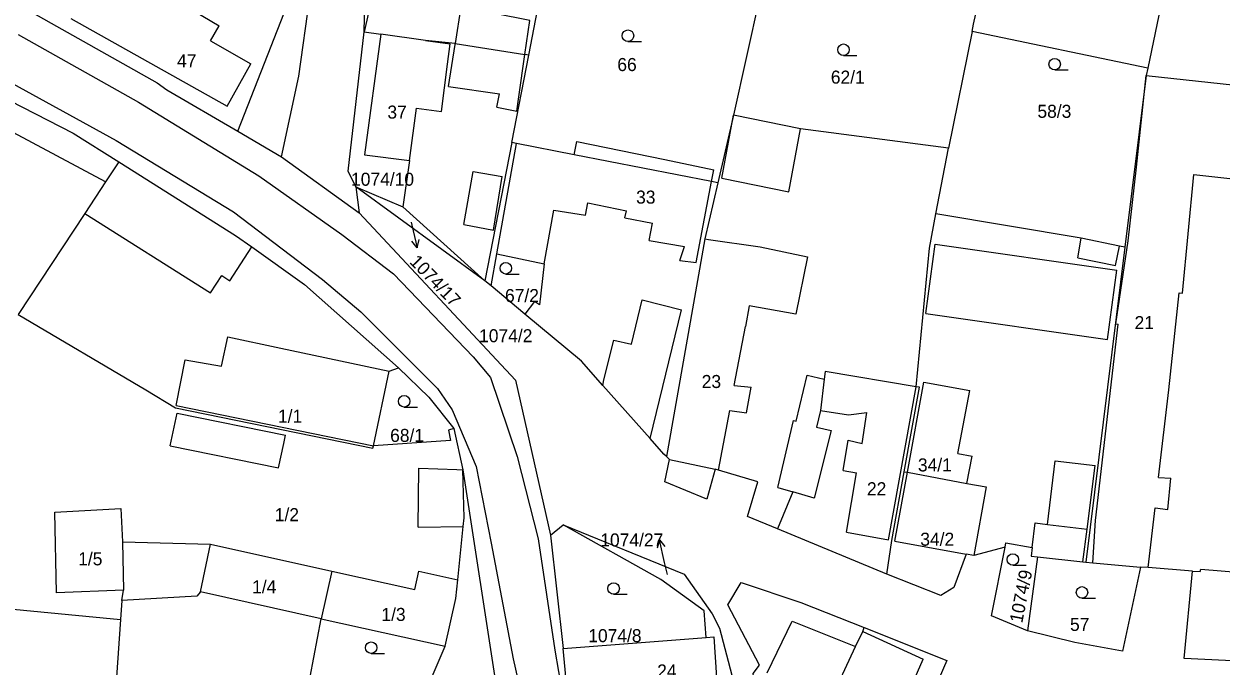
# Model space of a CAD drawing. Extents: x -746176 to -739709, y -1128407 to -1124482.
# Drawn here: x -742393.3 to -742237.2, y -1126052.3 to -1125968.5 of the extents above; entities that cross this region are included whole.
import ezdxf

# ---------------------------------------------------------------- set-up
doc = ezdxf.new("R2010")
doc.units = 0
for name, color, linetype in [('Hranice parcel', 7, 'Continuous'), ('Parcelní čísla', 7, 'Continuous'), ('Pop  PČ popisy', 7, 'Continuous'), ('Vnitřní kresba', 7, 'Continuous'), ('Značky kultur', 7, 'Continuous')]:
    doc.layers.add(name, color=color, linetype=linetype)

msp = doc.modelspace()

# ---------------------------------------------------------------- linework, layer by layer
at = {"layer": 'Hranice parcel'}
for p, q in [((-742296.81, -1125962.38), (-742300.78, -1125980.44)), ((-742244.64, -1125964.23), (-742246.75, -1125974.33)), ((-742348.95, -1125969.57), (-742346.78, -1125969.9)), ((-742269.67, -1125969.51), (-742272.76, -1125984.75)), ((-742246.75, -1125974.33), (-742269.67, -1125969.51)), ((-742329.7, -1125984.02), (-742327.47, -1125972.62)), ((-742246.94, -1125975.25), (-742249.72, -1125997.65)), ((-742246.75, -1125974.33), (-742246.94, -1125975.25)), ((-742246.94, -1125975.25), (-742222.55, -1125977.95)), ((-742300.78, -1125980.44), (-742302.83, -1125989.25)), ((-742329.7, -1125984.02), (-742333.21, -1126002.03)), ((-742274.38, -1125993.3), (-742272.76, -1125984.75)), ((-742380.97, -1125986.53), (-742382.69, -1125989.14)), ((-742350.03, -1125989.81), (-742343.92, -1125992.41)), ((-742333.21, -1126002.03), (-742350.03, -1125989.81)), ((-742350.03, -1125989.81), (-742349.63, -1125993.16)), ((-742343.92, -1125992.41), (-742333.21, -1126002.03)), ((-742275.24, -1125997.79), (-742274.38, -1125993.3)), ((-742276.95, -1126015.87), (-742275.24, -1125997.79)), ((-742249.72, -1125997.65), (-742254.82, -1126038.74)), ((-742332.39, -1126002.71), (-742333.21, -1126002.03)), ((-742327.99, -1126006.38), (-742332.39, -1126002.71)), ((-742337.26, -1126021.33), (-742336.07, -1126026.71)), ((-742336.07, -1126026.71), (-742330.17, -1126065.29)), ((-742324.67, -1126035.23), (-742323.01, -1126033.89)), ((-742280.77, -1126040.3), (-742295.06, -1126034.41)), ((-742324.67, -1126035.23), (-742323.01, -1126050.01)), ((-742265.36, -1126036.8), (-742269.44, -1126037.88)), ((-742261.12, -1126038.05), (-742262.44, -1126047.69)), ((-742353.18, -1126039.91), (-742354.56, -1126046.13)), ((-742354.56, -1126046.13), (-742370.32, -1126042.62)), ((-742356, -1126053.72), (-742354.56, -1126046.13)), ((-742354.56, -1126046.13), (-742338.41, -1126049.72)), ((-742323.01, -1126050.01), (-742304.36, -1126048.56)), ((-742341.65, -1126057.29), (-742338.41, -1126049.72))]:
    msp.add_line(p, q, dxfattribs=at)
for points in [[(-742348.95, -1125969.57), (-742348.77, -1125961.93), (-742341.73, -1125932.77)], [(-742444.75, -1125953.11), (-742386.93, -1125982.77), (-742380.97, -1125986.53)], [(-742345.34, -1125953.5), (-742347.31, -1125962.26), (-742348.95, -1125969.57)], [(-742382.69, -1125989.14), (-742398.6, -1125980.67), (-742445.94, -1125955.65)], [(-742327.47, -1125972.62), (-742326.77, -1125969.01), (-742324.69, -1125958.1)], [(-742365.43, -1125982.55), (-742356.37, -1125959.31), (-742357.41, -1125958.73)], [(-742269.67, -1125969.51), (-742269.48, -1125968.58), (-742268.65, -1125964.88)], [(-742392.86, -1125966.72), (-742375.94, -1125976.23), (-742374.7, -1125977.14), (-742365.43, -1125982.55)], [(-742327.47, -1125972.62), (-742328.01, -1125972.53), (-742327.37, -1125968.09), (-742336.35, -1125966.33), (-742337.09, -1125971.11), (-742340.95, -1125970.71), (-742346.78, -1125969.9)], [(-742350.03, -1125989.81), (-742351.04, -1125987.76), (-742348.95, -1125969.57)], [(-742346.78, -1125969.9), (-742348.93, -1125985.62), (-742343.03, -1125986.37), (-742343.92, -1125992.41)], [(-742272.76, -1125984.75), (-742292.04, -1125982.23), (-742300.78, -1125980.44)], [(-742365.43, -1125982.55), (-742359.74, -1125985.87), (-742349.63, -1125993.16)], [(-742302.83, -1125989.25), (-742303.65, -1125989.09), (-742321.55, -1125985.61), (-742329.11, -1125984.14), (-742329.7, -1125984.02)], [(-742380.97, -1125986.53), (-742365.73, -1125996.13), (-742363.63, -1125997.63), (-742356.74, -1126002.55), (-742344.5, -1126013.38)], [(-742382.69, -1125989.14), (-742385.4, -1125993.25), (-742394.08, -1126006.45)], [(-742302.83, -1125989.25), (-742304.53, -1125996.56), (-742309.51, -1126024.97)], [(-742349.63, -1125993.16), (-742329.2, -1126015.02), (-742324.67, -1126035.23)], [(-742249.72, -1125997.65), (-742250.44, -1125997.51), (-742255.43, -1125996.5), (-742274.38, -1125993.3)], [(-742332.39, -1126002.71), (-742331.66, -1125998.55), (-742325.47, -1125999.83), (-742326.09, -1126005.17), (-742326.73, -1126004.75), (-742327.99, -1126006.38)], [(-742394.08, -1126006.45), (-742377.42, -1126016.26), (-742373.55, -1126018.6), (-742347.83, -1126023.87), (-742347.76, -1126023.57)], [(-742309.51, -1126024.97), (-742309.85, -1126024.64), (-742311.67, -1126022.6), (-742317.81, -1126015.69), (-742320.62, -1126012.53), (-742327.99, -1126006.38)], [(-742347.76, -1126023.57), (-742345.71, -1126013.84), (-742344.5, -1126013.38)], [(-742344.5, -1126013.38), (-742340.52, -1126017.22), (-742337.26, -1126021.33)], [(-742276.95, -1126015.87), (-742288.82, -1126013.86), (-742288.94, -1126014.86), (-742289.42, -1126018.96), (-742289.94, -1126021.12), (-742288.05, -1126021.59), (-742290.26, -1126030.39), (-742293.05, -1126029.57), (-742295.06, -1126034.41)], [(-742278.52, -1126026.95), (-742276.54, -1126015.94), (-742276.95, -1126015.87)], [(-742337.26, -1126021.33), (-742337.97, -1126021.51), (-742337.68, -1126022.88), (-742347.76, -1126023.57)], [(-742295.06, -1126034.41), (-742298.95, -1126032.8), (-742297.59, -1126028.26), (-742302.72, -1126026.73), (-742303.16, -1126026.63), (-742304.27, -1126030.53), (-742309.75, -1126028.26), (-742309.14, -1126025.34), (-742309.51, -1126024.97)], [(-742336.75, -1126041.07), (-742336.05, -1126034.11), (-742335.93, -1126032.98), (-742336.07, -1126026.71)], [(-742280.77, -1126040.3), (-742280.14, -1126035.91), (-742278.52, -1126026.95)], [(-742278.52, -1126026.95), (-742278.1, -1126027.02), (-742270.33, -1126028.47), (-742267.82, -1126028.93), (-742269.44, -1126037.88)], [(-742389.08, -1126042.73), (-742389.31, -1126032.23), (-742380.68, -1126031.76), (-742380.48, -1126036.11), (-742380.34, -1126042.38), (-742389.08, -1126042.73)], [(-742304.36, -1126048.56), (-742304.63, -1126045.08), (-742310.25, -1126041.01), (-742323.01, -1126033.89)], [(-742323.01, -1126033.89), (-742307.21, -1126040.31), (-742303.55, -1126045.47), (-742302.63, -1126047.36), (-742301.01, -1126053.5), (-742299.94, -1126062.42)], [(-742370.32, -1126042.62), (-742368.99, -1126036.39), (-742353.18, -1126039.91)], [(-742265.36, -1126036.8), (-742265.25, -1126036.21), (-742261.83, -1126036.83), (-742261.97, -1126037.96), (-742261.12, -1126038.05)], [(-742269.44, -1126037.88), (-742270.44, -1126037.69), (-742272.05, -1126042.07), (-742273.73, -1126043.08), (-742280.77, -1126040.3)], [(-742262.44, -1126047.69), (-742267.12, -1126045.73), (-742265.36, -1126036.8)], [(-742261.12, -1126038.05), (-742255.21, -1126038.69), (-742254.82, -1126038.74)], [(-742247.69, -1126039.39), (-742250.03, -1126050.34), (-742256.28, -1126049.23), (-742262.44, -1126047.69)], [(-742254.82, -1126038.74), (-742253.91, -1126038.83), (-742247.69, -1126039.39)], [(-742240.91, -1126039.92), (-742246.7, -1126039.43), (-742247.69, -1126039.39)], [(-742240.91, -1126039.92), (-742239.93, -1126039.95), (-742239.83, -1126039.64), (-742234.01, -1126040.12), (-742233.11, -1126040.21), (-742233.15, -1126040.51), (-742227.7, -1126041.18), (-742227.29, -1126038.4), (-742226.7, -1126038.48)], [(-742353.18, -1126039.91), (-742342.34, -1126042.31), (-742341.81, -1126039.93), (-742336.75, -1126041.07)], [(-742338.41, -1126049.72), (-742336.99, -1126043.5), (-742336.75, -1126041.07)], [(-742222.2, -1126052.27), (-742242, -1126051.32), (-742240.91, -1126039.92)], [(-742370.32, -1126042.62), (-742370.8, -1126043.17), (-742380.56, -1126043.75), (-742380.73, -1126046.24)], [(-742293.29, -1126066.63), (-742294.4, -1126065.54), (-742295.46, -1126063.33), (-742297.55, -1126057.25), (-742298.22, -1126053.27), (-742297.41, -1126052.17), (-742301.53, -1126044.31), (-742299.77, -1126041.41), (-742291.99, -1126043.99), (-742283.72, -1126047.27)], [(-742408.01, -1126059.51), (-742408.36, -1126043.59), (-742380.73, -1126046.24)], [(-742380.73, -1126046.24), (-742381.25, -1126053.76), (-742374.55, -1126064.02)], [(-742293.29, -1126066.63), (-742290.54, -1126062.33), (-742288.73, -1126063.39), (-742289.27, -1126059.25), (-742288.22, -1126056.95), (-742284.85, -1126049.74), (-742283.92, -1126047.8), (-742283.72, -1126047.27)], [(-742283.72, -1126047.27), (-742272.96, -1126051.59), (-742278.82, -1126065.11), (-742280.26, -1126067.67), (-742280.55, -1126068.19), (-742283.01, -1126072.54), (-742293.29, -1126066.63)], [(-742304.36, -1126048.56), (-742303.36, -1126048.48), (-742302.98, -1126053.8), (-742302.95, -1126054.3), (-742299.94, -1126062.42)], [(-742314.1, -1126079.89), (-742322.45, -1126055.94), (-742323.01, -1126050.01)]]:
    msp.add_lwpolyline(points, dxfattribs=at)
at = {"layer": 'Pop  PČ popisy'}
for p, q in [((-742342.81, -1125994.4), (-742342.72, -1125994.81)), ((-742342.72, -1125994.81), (-742342.05, -1125997.73)), ((-742342.05, -1125997.73), (-742342.76, -1125996.87)), ((-742342.05, -1125997.73), (-742341.78, -1125996.65)), ((-742310.45, -1126035.85), (-742310.72, -1126036.93)), ((-742309.78, -1126038.77), (-742310.45, -1126035.85)), ((-742310.45, -1126035.85), (-742309.74, -1126036.71)), ((-742309.4, -1126040.35), (-742309.78, -1126038.77))]:
    msp.add_line(p, q, dxfattribs=at)
at = {"layer": 'Vnitřní kresba'}
for p, q in [((-742357.49, -1125975.36), (-742355.32, -1125959.9)), ((-742372.12, -1125966.26), (-742367.86, -1125968.77)), ((-742387.23, -1125967.82), (-742366.83, -1125979.29)), ((-742368.99, -1125970.76), (-742367.86, -1125968.77)), ((-742394.08, -1125969.92), (-742378.39, -1125978.73)), ((-742368.99, -1125970.76), (-742363.74, -1125973.74)), ((-742340.95, -1125970.71), (-742337.72, -1125971.14)), ((-742338.07, -1125973.8), (-742337.72, -1125971.14)), ((-742337.96, -1125976.7), (-742337.11, -1125971.22)), ((-742337.11, -1125971.22), (-742337.09, -1125971.11)), ((-742337.09, -1125971.11), (-742328.01, -1125972.53)), ((-742366.83, -1125979.29), (-742363.74, -1125973.74)), ((-742338.88, -1125979.98), (-742338.07, -1125973.8)), ((-742328.8, -1125978.06), (-742328.01, -1125972.53)), ((-742396.61, -1125975.35), (-742381.3, -1125983.74)), ((-742359.74, -1125985.87), (-742357.49, -1125975.36)), ((-742248.23, -1125987.21), (-742246.94, -1125975.25)), ((-742337.96, -1125976.7), (-742331.3, -1125977.68)), ((-742331.65, -1125979.39), (-742331.3, -1125977.68)), ((-742329.05, -1125979.9), (-742328.8, -1125978.06)), ((-742378.39, -1125978.73), (-742362.72, -1125988.35)), ((-742343.03, -1125986.37), (-742342.12, -1125979.52)), ((-742342.12, -1125979.52), (-742338.88, -1125979.98)), ((-742331.65, -1125979.39), (-742329.46, -1125979.82)), ((-742329.46, -1125979.82), (-742329.05, -1125979.9)), ((-742302.32, -1125988.68), (-742300.78, -1125980.44)), ((-742293.57, -1125990.45), (-742292.04, -1125982.23)), ((-742381.3, -1125983.74), (-742366, -1125993.07)), ((-742331.66, -1125998.55), (-742329.11, -1125984.14)), ((-742321.55, -1125985.61), (-742321.2, -1125983.86)), ((-742321.2, -1125983.86), (-742309.76, -1125986.21)), ((-742309.76, -1125986.21), (-742303.37, -1125987.59)), ((-742335.98, -1125994.7), (-742334.74, -1125987.77)), ((-742334.74, -1125987.77), (-742330.95, -1125988.45)), ((-742303.65, -1125989.09), (-742303.37, -1125987.59)), ((-742249.31, -1125996.84), (-742248.23, -1125987.21)), ((-742362.72, -1125988.35), (-742351.88, -1125995.99)), ((-742332.11, -1125995.44), (-742330.95, -1125988.45)), ((-742305.64, -1125999.67), (-742303.65, -1125989.09)), ((-742302.32, -1125988.68), (-742293.57, -1125990.45)), ((-742242.22, -1126003.67), (-742240.74, -1125988.18)), ((-742240.74, -1125988.18), (-742220, -1125990.44)), ((-742320.07, -1125993.48), (-742319.78, -1125991.88)), ((-742319.78, -1125991.88), (-742314.76, -1125992.93)), ((-742385.4, -1125993.25), (-742369.01, -1126003.63)), ((-742366, -1125993.07), (-742354.38, -1126001.86)), ((-742325.47, -1125999.83), (-742324.24, -1125992.82)), ((-742324.24, -1125992.82), (-742320.07, -1125993.48)), ((-742314.94, -1125993.84), (-742314.76, -1125992.93)), ((-742314.94, -1125993.84), (-742311.35, -1125994.55)), ((-742335.98, -1125994.7), (-742332.11, -1125995.44)), ((-742311.78, -1125996.77), (-742311.35, -1125994.55)), ((-742351.88, -1125995.99), (-742345.15, -1126001.12)), ((-742311.78, -1125996.77), (-742307.18, -1125997.57)), ((-742304.53, -1125996.56), (-742304.04, -1125996.64)), ((-742304.04, -1125996.64), (-742297.32, -1125997.63)), ((-742275.68, -1126006.29), (-742274.46, -1125997.29)), ((-742274.46, -1125997.29), (-742250.78, -1126000.65)), ((-742255.88, -1125999.05), (-742255.43, -1125996.5)), ((-742250.91, -1126007.68), (-742249.31, -1125996.84)), ((-742366.46, -1126002.04), (-742363.63, -1125997.63)), ((-742307.77, -1125999.4), (-742307.18, -1125997.57)), ((-742250.94, -1126000.04), (-742250.44, -1125997.51)), ((-742307.77, -1125999.4), (-742305.64, -1125999.67)), ((-742255.88, -1125999.05), (-742250.94, -1126000.04)), ((-742369.01, -1126003.63), (-742367.52, -1126001.35)), ((-742367.52, -1126001.35), (-742366.46, -1126002.04)), ((-742354.38, -1126001.86), (-742349.4, -1126006.1)), ((-742345.15, -1126001.12), (-742334.74, -1126011.95)), ((-742252.01, -1126009.69), (-742250.78, -1126000.65)), ((-742244, -1126016.27), (-742242.65, -1126003.62)), ((-742242.65, -1126003.62), (-742242.22, -1126003.67)), ((-742314.11, -1126010.3), (-742312.7, -1126004.51)), ((-742312.7, -1126004.51), (-742307.56, -1126005.82)), ((-742349.4, -1126006.1), (-742339.39, -1126016.09)), ((-742311.67, -1126022.6), (-742307.56, -1126005.82)), ((-742275.68, -1126006.29), (-742252.01, -1126009.69)), ((-742300.68, -1126015.71), (-742299.24, -1126007.99)), ((-742253.57, -1126033.31), (-742250.61, -1126007.72)), ((-742250.91, -1126007.68), (-742250.61, -1126007.72)), ((-742367.58, -1126013.2), (-742366.76, -1126009.36)), ((-742366.76, -1126009.36), (-742359.84, -1126010.83)), ((-742317.68, -1126014.95), (-742316.39, -1126009.79)), ((-742316.39, -1126009.79), (-742314.11, -1126010.3)), ((-742359.84, -1126010.83), (-742356.97, -1126011.42)), ((-742356.97, -1126011.42), (-742345.71, -1126013.84)), ((-742373.49, -1126018.3), (-742372.32, -1126012.36)), ((-742372.32, -1126012.36), (-742367.58, -1126013.2)), ((-742334.74, -1126011.95), (-742332.47, -1126014.68)), ((-742292.61, -1126020.36), (-742291.18, -1126014.35)), ((-742291.18, -1126014.35), (-742288.94, -1126014.86)), ((-742339.39, -1126016.09), (-742337.47, -1126018.89)), ((-742332.47, -1126014.68), (-742328.99, -1126024.95)), ((-742317.81, -1126015.69), (-742317.68, -1126014.95)), ((-742300.68, -1126015.71), (-742298.47, -1126015.93)), ((-742299.1, -1126019.25), (-742298.47, -1126015.93)), ((-742280.55, -1126035.82), (-742276.95, -1126015.87)), ((-742278.1, -1126027.02), (-742275.97, -1126015.26)), ((-742275.97, -1126015.26), (-742269.97, -1126016.35)), ((-742271.51, -1126024.59), (-742269.97, -1126016.35)), ((-742245.33, -1126027.71), (-742244, -1126016.27)), ((-742373.49, -1126018.3), (-742347.76, -1126023.57)), ((-742337.47, -1126018.89), (-742334.36, -1126026.25)), ((-742302.72, -1126026.73), (-742301.28, -1126018.98)), ((-742301.28, -1126018.98), (-742299.1, -1126019.25)), ((-742289.42, -1126018.96), (-742285.79, -1126019.55)), ((-742285.79, -1126019.55), (-742283.38, -1126019.23)), ((-742284.01, -1126023.25), (-742283.38, -1126019.23)), ((-742374.27, -1126023.57), (-742373.33, -1126019.33)), ((-742373.33, -1126019.33), (-742359.21, -1126022.18)), ((-742295.01, -1126028.99), (-742292.95, -1126020.28)), ((-742292.95, -1126020.28), (-742292.61, -1126020.36)), ((-742359.45, -1126023.28), (-742359.21, -1126022.18)), ((-742374.27, -1126023.57), (-742360.14, -1126026.43)), ((-742360.14, -1126026.43), (-742359.45, -1126023.28)), ((-742286.5, -1126026.79), (-742285.82, -1126022.85)), ((-742285.82, -1126022.85), (-742284.01, -1126023.25)), ((-742328.99, -1126024.95), (-742326.26, -1126035.72)), ((-742309.14, -1126025.34), (-742303.16, -1126026.63)), ((-742271.51, -1126024.59), (-742269.67, -1126024.93)), ((-742270.33, -1126028.47), (-742269.67, -1126024.93)), ((-742259.83, -1126033.82), (-742258.82, -1126025.53)), ((-742258.82, -1126025.53), (-742253.6, -1126026.15)), ((-742341.9, -1126034.19), (-742341.81, -1126026.49)), ((-742341.81, -1126026.49), (-742336.86, -1126026.68)), ((-742336.86, -1126026.68), (-742336.07, -1126026.71)), ((-742334.36, -1126026.25), (-742332.41, -1126036.26)), ((-742286.5, -1126026.79), (-742284.74, -1126027.11)), ((-742286.06, -1126034.83), (-742284.74, -1126027.11)), ((-742279.73, -1126036), (-742278.1, -1126027.02)), ((-742254.67, -1126034.46), (-742253.6, -1126026.15)), ((-742245.33, -1126027.71), (-742243.73, -1126027.81)), ((-742244.14, -1126031.87), (-742243.73, -1126027.81)), ((-742295.01, -1126028.99), (-742293.05, -1126029.57)), ((-742246.7, -1126039.43), (-742245.79, -1126031.64)), ((-742245.79, -1126031.64), (-742244.14, -1126031.87)), ((-742253.91, -1126038.83), (-742253.57, -1126033.31)), ((-742341.9, -1126034.19), (-742336.05, -1126034.11)), ((-742286.06, -1126034.83), (-742280.55, -1126035.82)), ((-742261.83, -1126036.83), (-742261.42, -1126033.63)), ((-742261.42, -1126033.63), (-742259.83, -1126033.82)), ((-742259.83, -1126033.82), (-742254.67, -1126034.46)), ((-742255.21, -1126038.69), (-742254.67, -1126034.46)), ((-742380.48, -1126036.11), (-742368.99, -1126036.39)), ((-742332.41, -1126036.26), (-742329.51, -1126051.35)), ((-742326.26, -1126035.72), (-742324.08, -1126050.22)), ((-742279.73, -1126036), (-742270.44, -1126037.69)), ((-742380.56, -1126043.75), (-742380.34, -1126042.38)), ((-742296.38, -1126053.19), (-742293.13, -1126046.42)), ((-742293.13, -1126046.42), (-742284.85, -1126049.74)), ((-742283.92, -1126047.8), (-742276.03, -1126051.39)), ((-742324.08, -1126050.22), (-742321.93, -1126062.83)), ((-742329.51, -1126051.35), (-742326.67, -1126064.04)), ((-742278.04, -1126055.93), (-742276.03, -1126051.39))]:
    msp.add_line(p, q, dxfattribs=at)
msp.add_lwpolyline([(-742297.32, -1125997.63), (-742291.14, -1125998.94), (-742292.67, -1126006.4), (-742298.74, -1126005.29), (-742299.24, -1126007.99)], dxfattribs=at)
at = {"layer": 'Značky kultur'}
for p, q in [((-742314.55, -1125970.83), (-742312.8, -1125970.83)), ((-742286.43, -1125972.66), (-742284.68, -1125972.66)), ((-742258.89, -1125974.54), (-742257.14, -1125974.54)), ((-742330.49, -1126001.16), (-742328.74, -1126001.16)), ((-742343.74, -1126018.51), (-742341.99, -1126018.51)), ((-742264.34, -1126039.14), (-742262.59, -1126039.14)), ((-742316.42, -1126042.93), (-742314.67, -1126042.93)), ((-742255.33, -1126043.44), (-742253.58, -1126043.44)), ((-742348.04, -1126050.65), (-742346.29, -1126050.65))]:
    msp.add_line(p, q, dxfattribs=at)
for centre in [(-742314.55, -1125970.08), (-742286.43, -1125971.91), (-742258.89, -1125973.79), (-742330.49, -1126000.41), (-742343.74, -1126017.76), (-742264.34, -1126038.39), (-742316.42, -1126042.18), (-742255.33, -1126042.69), (-742348.04, -1126049.9)]:
    msp.add_circle(centre, 0.75, dxfattribs=at)

# ---------------------------------------------------------------- texts
at = {"layer": 'Parcelní čísla'}
for s, p in [('47', (-742373.37, -1125974.21)), ('66', (-742315.94, -1125974.69)), ('62/1', (-742288.09, -1125976.33)), ('37', (-742345.93, -1125980.89)), ('58/3', (-742261.14, -1125980.79)), ('1074/10', (-742350.67, -1125989.65)), ('33', (-742313.49, -1125991.98)), ('67/2', (-742330.59, -1126004.82)), ('21', (-742248.47, -1126008.35)), ('1074/2', (-742333.97, -1126010.06)), ('23', (-742304.93, -1126016.03)), ('1/1', (-742360.2, -1126020.55)), ('68/1', (-742345.57, -1126023.06)), ('34/1', (-742276.73, -1126026.91)), ('22', (-742283.38, -1126030.02)), ('1/2', (-742360.62, -1126033.4)), ('1074/27', (-742318.16, -1126036.7)), ('34/2', (-742276.42, -1126036.6)), ('1/5', (-742386.26, -1126039.16)), ('1/4', (-742363.57, -1126042.8)), ('1/3', (-742346.71, -1126046.41)), ('1074/8', (-742319.73, -1126049.18)), ('57', (-742256.89, -1126047.71)), ('24', (-742310.74, -1126053.79))]:
    msp.add_text(s, height=1.7, dxfattribs=at).set_placement(p)
for s, rotation, p in [('1074/17', 314, (-742343.14, -1125999.65)), ('1074/9', 79, (-742263.12, -1126046.76))]:
    msp.add_text(s, height=1.7, rotation=rotation, dxfattribs=at).set_placement(p)

doc.saveas('drawing.dxf')
